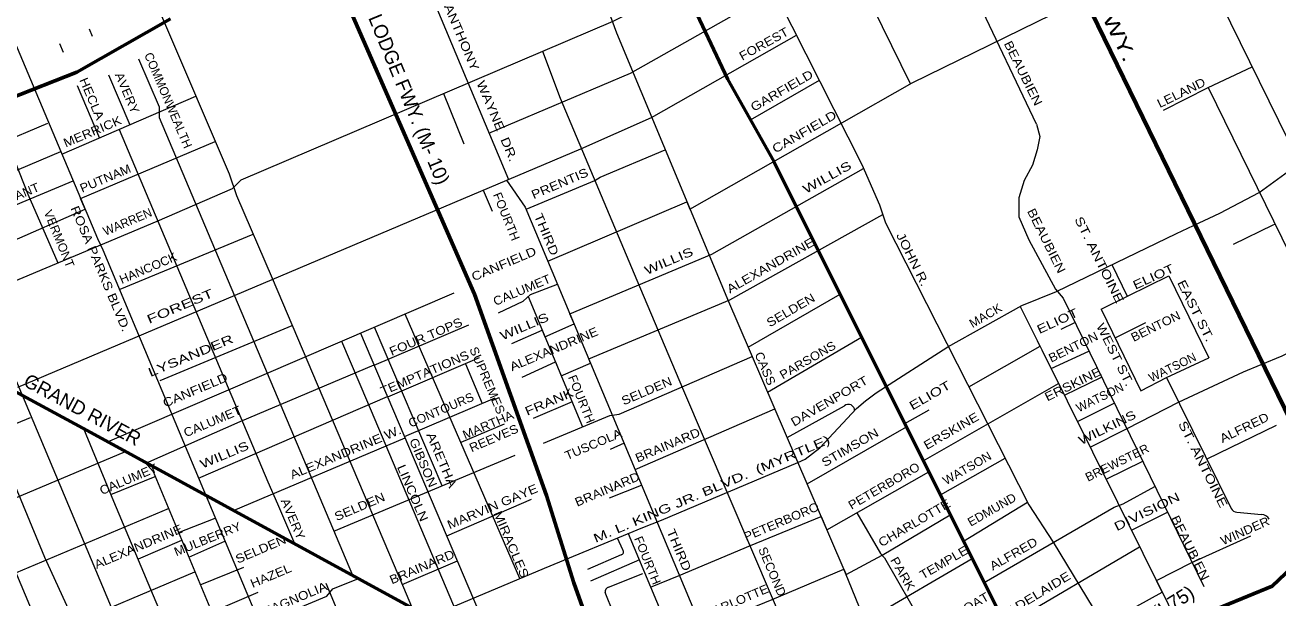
# Model space of a CAD drawing. Extents: x 34705 to 138605, y 34275 to 143551.
# Drawn here: x 89542 to 100351, y 103945 to 108885 of the extents above; entities that cross this region are included whole.
import ezdxf
from ezdxf.enums import TextEntityAlignment as Align

# ---------------------------------------------------------------- set-up
doc = ezdxf.new("R2010")
doc.units = 0
doc.header["$LTSCALE"] = 30
for name, color, linetype, lineweight in [('1', 7, 'Continuous', 13), ('11', 7, 'Continuous', 13), ('51', 7, 'Continuous', 35)]:
    doc.layers.add(name, color=color, linetype=linetype, lineweight=lineweight)

msp = doc.modelspace()

# ---------------------------------------------------------------- linework, layer by layer
at = {"layer": '1'}
for p, q in [((98268.09, 108031.24), (96714.25, 111289.53)), ((97195.08, 108386.28), (98669.87, 109111.42)), ((90094.68, 108851.47), (90120.89, 108789.79)), ((89838.85, 108726.79), (89871.1, 108650.47)), ((99750.13, 108345.09), (100128.24, 108524.33)), ((90262.96, 108455.55), (90446.24, 108024.38)), ((89992.73, 108362.68), (90183.76, 107910.7)), ((95800.35, 108066.32), (96394.86, 108409.99)), ((93152.95, 108294.54), (93327.47, 107861.91)), ((89063.37, 107752.52), (89737.65, 108039.92)), ((88037.22, 107540.27), (90948.84, 100639.76)), ((89271.92, 107254.92), (89956.65, 107542.35)), ((93494.54, 107462.47), (93571.5, 107280.51)), ((99476.25, 107088.15), (99622.96, 107156.95)), ((90361.57, 106607.54), (91510.38, 107081.43)), ((98919.57, 106819.11), (99051.55, 106546.97)), ((99060.17, 106551.15), (99410.54, 106722.32)), ((99410.54, 106722.32), (99755.93, 106015.44)), ((90254.41, 105291.57), (93244.99, 106574.95)), ((93882.8, 106543.11), (94351.99, 105420.76)), ((95780.55, 106107.06), (96574.52, 106563.39)), ((98826.13, 106434.13), (99060.17, 106551.15)), ((93812.34, 104112.95), (92821.35, 106393.15)), ((98826.13, 106434.13), (99169.3, 105731.8)), ((90707.67, 105821), (91848, 106294.07)), ((92555.43, 105951.17), (93372.26, 106299.14)), ((93140.31, 104911.52), (92557.83, 106280.07)), ((98482.05, 106262.07), (98599.25, 106320.68)), ((98945.95, 106188.91), (99210.33, 106321.11)), ((92437.6, 106228.47), (93613.46, 103461.04)), ((95948.17, 105718.52), (96759.8, 106192.63)), ((98299.54, 106114.59), (98277.06, 106159.57)), ((97685.09, 105764.32), (98299.54, 106114.59)), ((98395.14, 105922.3), (98720.71, 106072.11)), ((92671.46, 105678.09), (93464.13, 106017.69)), ((93341.29, 105965.06), (93486.33, 105622.5)), ((98508.94, 105692.45), (98829.38, 105849.71)), ((99389.68, 105844.93), (99949.07, 104716.79)), ((96792.71, 105644.68), (96885.15, 105714.56)), ((97291.93, 105127.73), (98458.89, 105793.94)), ((91038.93, 104979), (92670.27, 105680.89)), ((92815.81, 105338.34), (93598.22, 105669.92)), ((94261.97, 105636.08), (93926.96, 105492.82)), ((96716.8, 105577.81), (96792.71, 105644.68)), ((98621.13, 105467.27), (98939.78, 105623.75)), ((87940.41, 104815.15), (89589.87, 105502.16)), ((94805.77, 105052.37), (96009.93, 105575.32)), ((96115.98, 105329.5), (96610.87, 105602.03)), ((97131.52, 105448.74), (97341.23, 105568.3)), ((93674.78, 105442.79), (93303.16, 105284.53)), ((96289.23, 104927.89), (97145.81, 105420.13)), ((99739.75, 105143.49), (100339.65, 105434.57)), ((91340.91, 104699.96), (92821.66, 105324.57)), ((94710.75, 105279.08), (94589.3, 105224.13)), ((92207.61, 104519.53), (93772.07, 105177.04)), ((95033.53, 104614.61), (96209.46, 105112.79)), ((96209.46, 105112.79), (96273.4, 105140.29)), ((97439.28, 104832.85), (97997.48, 105150.12)), ((98868.77, 104968.69), (99184.41, 105123.1)), ((90281.25, 104836.21), (90665.41, 104992.53)), ((94585.62, 104809.59), (94862, 104918.2)), ((93180.91, 104479.06), (93911.95, 104795.23)), ((97637.63, 104435.9), (98189.75, 104772.08)), ((87580.9, 103369.15), (90780.2, 104717.28)), ((90866.81, 104508.8), (91183.12, 104633.11)), ((99086.69, 104529.92), (99398.13, 104685.69)), ((99997.85, 104684.82), (100209.21, 104664.52)), ((94870.72, 104551.4), (95033.53, 104614.61)), ((90521.46, 104281.06), (90894.05, 104443.38)), ((90954.85, 104297.34), (91266.47, 104434.49)), ((94700.64, 104358.37), (94652.42, 104461.37)), ((94745.68, 104500.34), (95648.75, 102345.66)), ((94686.23, 104316.6), (94395.44, 104191.29)), ((98002.36, 103706.01), (99158.2, 104385.92)), ((91054.04, 104059.11), (91428.49, 104211.27)), ((92796.63, 104061.99), (93272.21, 104264.18)), ((94843.86, 104272.69), (94420.3, 104088.29)), ((96956.14, 104289.35), (97774.44, 102874.49)), ((92198.44, 104022.64), (92418.5, 104112.49)), ((94577.26, 104038.12), (94871.2, 104156.65)), ((91152.1, 103823.55), (91552.57, 103996.12)), ((94619.68, 103812.39), (94546.47, 103991.39))]:
    msp.add_line(p, q, dxfattribs=at)
at = {"layer": '1', "lineweight": 53}
msp.add_line((90110.84, 105370.56), (94629.96, 102906.87), dxfattribs=at)
at = {"layer": '1'}
for points in [[(89474.59, 122846.01), (91544.38, 118695.87), (91485.34, 118525.26), (91445.98, 118334.96), (92122.6, 116967.52), (92180.3, 116877.74), (93371.26, 114453.63), (94086.27, 113029.71), (94119.06, 112950.97), (94335.54, 112517.89), (95799.33, 109586.03), (95857.03, 109444.94), (96036.54, 109117.87), (96762.63, 107683.46), (96913.51, 107335.68), (96965.99, 107178.2), (98202.49, 104747.04), (98412.4, 104425.51), (98930.62, 103572.47), (99211.35, 103092.72)], [(81747.75, 122290.24), (81921.27, 121957.09), (82052.47, 121930.85), (82118.06, 121884.91), (82590.36, 120959.69), (82629.72, 120926.88), (83141.38, 119927.85), (83541.52, 119133.87), (83541.52, 119022.31), (83495.61, 118937.01), (83436.57, 118877.95), (83449.69, 118733.59), (83456.25, 118661.41), (87277.28, 110821.66), (87605.27, 110172.03), (87736.46, 109929.24), (90285.3, 103864.22), (92725.99, 98068.68)], [(92090.21, 118673.57), (92344.66, 118157.79), (94015.45, 114820.73), (94775.04, 113275.79), (95103.02, 112606.48), (95332.61, 112140.59), (97179.3, 108381.96)], [(99622.96, 107156.95), (99848.68, 107262.79), (100188.92, 107440.65), (100537.2, 107693.33), (100968.9, 107962.79), (103779.62, 109348.23), (104572.5, 109741.16), (105072.96, 109985.65), (105247.54, 110090.43), (106097.16, 110492.09), (110265.23, 112549.88), (110957.73, 112899.15), (112028.48, 113475.45), (113105.05, 114057.56), (114210.72, 114761.93)], [(92402.65, 113894.18), (92751.37, 113182.28), (92816.97, 113064.17), (92902.24, 112946.05), (92967.84, 112775.44), (93151.51, 112329.24), (94584.81, 108982.71), (94643.84, 108818.66), (95260.46, 107342.24), (95601.56, 106522.01), (96598.64, 104210.61), (96644.56, 104099.06), (97018.46, 103180.4), (97300.53, 102491.4), (97891.97, 101138.22)], [(91170.47, 113339.76), (91288.55, 113261.02), (91767.41, 112276.74), (91819.89, 112125.82), (91839.57, 112020.83), (91905.16, 111784.6), (91964.2, 111600.87), (92101.96, 111312.15), (92213.47, 111134.98), (92285.63, 111016.87), (92416.82, 110733.08), (92672.65, 110175.32), (92725.13, 109958.78), (92803.85, 109722.55), (93711.92, 107554.46)], [(87924.47, 112104.52), (87935.44, 111856.64), (88221.88, 111308.88), (88769.61, 110355.76), (90167.23, 107043.23), (90212.11, 106947.03), (92757.3, 100881.83), (92968.86, 100445.74), (93020.15, 100349.54), (93007.33, 100272.59), (93410.61, 99313.84), (93470.43, 99278.08), (94003.29, 98018.06), (94007.57, 97912.37), (94251.36, 97332.72)], [(89620.31, 111530.82), (91301.99, 107601.17), (91366.1, 107415.19), (91673.83, 106703.33), (92808.58, 104033.88), (93975.39, 101263.41), (94552.01, 99871.59), (94676.64, 99628.81), (94945.59, 99182.6), (95948.05, 97457.03)], [(93544.68, 107953.77), (94766.98, 108470.68), (96621.13, 109518.01)], [(74914.4, 104874.31), (75879.58, 104897.58), (77259.02, 104781.25), (77456.7, 104757.99), (78323.04, 104711.46), (84801.63, 104845.23), (85092.35, 104868.5), (85377.25, 104932.47), (86652.03, 105479.2), (88419.59, 106217.85), (88564.94, 106305.1), (90681.35, 107194.97), (91332.56, 107474.15), (91408.14, 107549.76), (94615.68, 108918.91), (95226.7, 109227.44), (95367, 109272.3)], [(99858.25, 109072.97), (101846.54, 105032.72), (101949.12, 104782.61), (102115.8, 104423.47), (102367.74, 103949.45)], [(89480.37, 105763.72), (94336.35, 107818.71), (94947.38, 108086.49), (96198.55, 108797.8)], [(94005.91, 108658.63), (94158.42, 108254.34), (94820.96, 106686.06), (95214.54, 105754.27), (96190.89, 103469.22)], [(90522.15, 108593.43), (90698.17, 108180.52), (90698.17, 108088.65), (92367.36, 104140.37)], [(94052.23, 106850.36), (95252.26, 107361.86), (95278.76, 107298.24), (96589.88, 108042.83), (97195.08, 108386.28)], [(99364.51, 108152.23), (99750.13, 108345.09), (100384.82, 107049.64), (101453.37, 104861.55)], [(99364.51, 108152.23), (99750.13, 108345.09), (100384.82, 107049.64), (101442.45, 104883.91)], [(99364.51, 108152.23), (99750.13, 108345.09), (100384.82, 107049.64), (101464.42, 104838.92)], [(88822.18, 107335.87), (89175.45, 107491.6), (89204.52, 107520.68), (89849.99, 107795.14), (89860.49, 107770.24), (91015.38, 108270.9)], [(89306.48, 108074.95), (89566.63, 107427.55), (89826.05, 106835.35)], [(90355.43, 107985.05), (91636.21, 104947.17), (91721.49, 104756.87), (91867.34, 104412.97)], [(98268.09, 108031.24), (98296.43, 107925.03), (98274.65, 107808.14), (98235.29, 107676.9), (98163.13, 107545.66), (98117.21, 107394.74), (98117.21, 107230.69), (98202.49, 107033.84), (98432.08, 106607.32), (98497.68, 106528.57), (99711.23, 104044.92)], [(88986.64, 106954.4), (89336.78, 107100.15), (89379.83, 106997.43), (90060.09, 107297.16), (90021.38, 107388.91), (91182.55, 107880.27)], [(93864.6, 107298.05), (94458.56, 107545.12), (94505.11, 107574.22), (95065.61, 107808.79)], [(93742.41, 106137.57), (94003.94, 106253.34), (94027.36, 106197.32), (94278.8, 106309.76), (94243.06, 106395.04), (95466.53, 106909.98), (96774.75, 107648.64)], [(93695.7, 107547.6), (93857.2, 107315.71), (95985.91, 102236.51)], [(93830.01, 105849.94), (94118.32, 105979.73), (94168.42, 105859.88), (94421, 105970.47), (94406.15, 106005.88), (95623.51, 106514.48), (96941.38, 107252.03)], [(99967.16, 106994.24), (100311.32, 107162.37), (100324.93, 107169.07)], [(96885.15, 105714.56), (97503.51, 106110.2), (98140.51, 106466.1), (98440.41, 106587.53), (99476.25, 107088.15)], [(93627.3, 106404.33), (93838.52, 106502.85), (93902.48, 106561.01), (94136.06, 106650.35)], [(98127.48, 106458.82), (98314, 106085.66), (99403.93, 103891.18), (99544.97, 103583.35), (99595.15, 103504.77)], [(100207.62, 105958.03), (100386.97, 106033.07), (100771.04, 106225.17), (100840.88, 106265.91), (101155.71, 106436.5)], [(89318.01, 106151.54), (89120.57, 106072.53), (89061.53, 105947.86), (89061.53, 105862.55), (89709.3, 104295.91), (89979.33, 103708.16), (90424.31, 102635.76), (90450.55, 102570.15)], [(92273.44, 106158.02), (92495.54, 105632.89), (93356.65, 103601.04)], [(90584.73, 105107.33), (91399.42, 105467.56), (92553.8, 105955)], [(94015.76, 105279.45), (94586.58, 105519.35), (94668.05, 105530.99), (95814.89, 106027.46)], [(98730.8, 105246.46), (99051.44, 105405.83), (99493.71, 105632.86), (100054.7, 105894.04), (100207.62, 105958.03)], [(99169.3, 105731.8), (99389.9, 105845.04), (99755.93, 106015.44)], [(96273.4, 105140.29), (96399.9, 105238.19), (96716.8, 105577.81)], [(90045.33, 105405.98), (90304.59, 104779.85), (90859.58, 103460.99)], [(79819.31, 100347.1), (80849.35, 100888.78), (81157.51, 101063.26), (81390.09, 101179.59), (82385.53, 101727.1), (82404.38, 101691.59), (83852.83, 102468.28), (83914.13, 102353.8), (84532.72, 102680.17), (84619.93, 102761.59), (84869.95, 102889.55), (85242.07, 103052.4), (85300.21, 103052.4), (86410.74, 103506.06), (87338.12, 103914.64), (90408.69, 105206.69)], [(90576.58, 105116.66), (90647.47, 105035.61), (91251.37, 103585.13)], [(94939.42, 104038.08), (95184.51, 104139.73), (95801.36, 104395.86), (96410.38, 104647.02), (96459.66, 104532.78), (97340.13, 105031.27)], [(97817.09, 104076.77), (98939.76, 104727.12), (99015.56, 104757.45), (99290.52, 104905.94)], [(95144.29, 103549.28), (95370.73, 103656.57), (95446.38, 103708.96), (95987.58, 103930.16), (96605.73, 104193.38), (96625.21, 104146.06), (96936.12, 104314.36), (97524.26, 104662.79)], [(96717.5, 104678.76), (96923.34, 104328.72), (96956.14, 104289.35)], [(90156.4, 102571.65), (94024.26, 104202.29), (94870.72, 104551.4)], [(98181.84, 103346.84), (99351.96, 103995.82), (99302.9, 104094.6), (99608.67, 104250.66), (100118.87, 104480.34)], [(90738.5, 101138.28), (92958.63, 102086.3), (93540.56, 102319.15), (94588.03, 102755.74), (94861.54, 102907.09), (96744.08, 103703.14), (96837.19, 103772.99), (97713.93, 104285.09)], [(87827, 102821.34), (88640.53, 103170.17), (91008.18, 104169.25)], [(91251.37, 103585.13), (92146.6, 103961.27), (92198.44, 104022.64)], [(92137.1, 104071.39), (93174.01, 101584.06), (93353.56, 101153.61)]]:
    msp.add_lwpolyline(points, dxfattribs=at)
at = {"layer": '1', "lineweight": 53}
for points in [[(88660.55, 122435.75), (92843.2, 114028.76), (93335.18, 113024.79), (93440.14, 112782.01), (93902.59, 111904.36), (94112.5, 111523.77), (94525.77, 110657.61), (94939.03, 109837.38), (95188.3, 109345.24), (95267.02, 109133.63), (95601.56, 108418.39), (96001.71, 107709.71), (99029.01, 101651.49), (99866.2, 100204.4)], [(81141.26, 110244.39), (85447.32, 107891.61), (90110.84, 105370.56)]]:
    msp.add_lwpolyline(points, dxfattribs=at)
at = {"layer": '1'}
for centre, radius, start, end in [((96645.05, 105560), 54.17, 358.90575, 129.11156), ((99999.82, 104741.02), 56.24, 205.5248, 267.9903), ((100210.68, 104592.46), 72.07, 26.80006, 91.17398), ((94678.15, 104342.76), 27.38, 287.16115, 34.7633), ((94591.96, 103994.93), 45.63, 108.79235, 184.44263)]:
    msp.add_arc(centre, radius, start, end, dxfattribs=at)
at = {"layer": '51', "lineweight": 60}
for points in [[(89237.66, 115479.85), (91499.64, 110952.67), (93420.76, 106565.37), (94042.42, 104827.01), (94275.43, 104074.61), (94754.53, 102737.63), (94761.52, 102513.8), (95607.58, 100567.59), (95901.26, 100112.95), (96166.96, 99847.16), (96705.36, 99210.66), (97075.95, 98895.9), (97236.78, 98686.07), (97390.6, 98581.15), (97562.53, 98387.67)], [(87067.87, 107328.8), (89988.97, 108477.92), (90798.22, 108939.62)], [(100708.3, 104431.99), (100301.7, 104046.37), (99460.75, 103701.33), (98388.89, 103068.27), (97510.88, 102543.58), (96878.03, 102018.88), (96266.56, 101672.41), (94157.06, 101062.17), (92788.73, 100605.91), (92053.25, 100332.16), (91322.06, 100332.16), (90426.94, 100400.6), (89697.17, 100337.86), (89332.28, 99932.93), (89286.67, 99488.08), (89309.48, 99071.74), (89383.59, 98792.29), (89913.82, 97593.19), (90193.19, 96937.32), (90347.13, 96349.89), (90369.93, 95910.74)]]:
    msp.add_lwpolyline(points, dxfattribs=at)
at = {"layer": '51', "lineweight": 70}
msp.add_lwpolyline([(97910.12, 110708.17), (100683.69, 105015.92), (100740.7, 104462.71), (100708.3, 104431.99)], dxfattribs=at)

# ---------------------------------------------------------------- texts
at = {"layer": '11'}
for s, height, rotation, width, p in [('CHRYSLER FWY.', 120, 296.26, 1.45, (98604.73, 109412.12)), ('ANTHONY   WAYNE  DR.', 75, 292.998, 1.25, (93440.68, 108372.61)), ('FOREST', 75, 29.017, 1.15, (95934.21, 108689.73)), ('BEAUBIEN', 75, 296.46, 1.2, (98120.07, 108453.33)), ('HECLA', 75, 293.107, 1.15, (90084.67, 108234.86)), ('AVERY', 75, 293.097, 1.1, (90389.05, 108284.85)), ('GARFIELD', 75, 30.017, 1.2, (96089.74, 108287.12)), ('LELAND', 75, 26.216, 1.15, (99533.59, 108267.59)), ('MERRICK', 75, 22.848, 1.15, (90138.02, 107932.49)), ('CANFIELD', 75, 30.018, 1.25, (96283.72, 107932.05)), ('PUTNAM', 75, 22.817, 1.1, (90249.5, 107528.75)), ('WILLIS', 75, 28.998, 1.4, (96479.78, 107539.5)), ('PRENTIS', 75, 22.997, 1.2, (94170.08, 107484.3)), ('BRYANT', 75, 22.808, 1.1, (89468.51, 107371.65)), ('FOURTH', 75, 292.14, 1.05, (93660.58, 107219.93)), ('VERMONT', 75, 292.318, 1.05, (89801.83, 107028.08)), ('ROSA PARKS BLVD.', 75, 292.857, 1.2, (90158.81, 106769.78)), ('THIRD', 75, 292.938, 1.25, (94006.49, 107065.53)), ('BEAUBIEN', 75, 296.46, 1.2, (98320.42, 107008.41)), ('ST. ANTOINE', 75, 296.46, 1.3, (98776.42, 106844.1)), ('ALEXANDRINE', 75, 29.753, 1.2, (95991.68, 106779.14)), ('JOHN R.', 75, 296.46, 1.25, (97167.39, 106848.9)), ('HANCOCK', 75, 23.196, 1.05, (90618.85, 106755.32)), ('CANFIELD', 75, 22.955, 1.2, (93687.33, 106790.96)), ('WILLIS', 75, 22.999, 1.35, (95110.21, 106815.93)), ('ELIOT', 75, 24.683, 1.3, (99292.42, 106681.04)), ('CALUMET', 75, 23.002, 1.1, (93843.08, 106565.53)), ('EAST ST.', 75, 296.46, 1.3, (99608.68, 106404.82)), ('FOREST       ', 75, 22.799, 1.5, (91028.86, 106482.49)), ('SELDEN', 75, 30.304, 1.15, (96166.58, 106393.62)), ('MACK', 75, 30.304, 1.05, (97847.54, 106347.61)), ('WILLIS', 75, 22.999, 1.35, (93864.46, 106251.68)), ('ELIOT', 75, 24.683, 1.3, (98464.44, 106298.91)), ('BENTON', 75, 26.24, 1.1, (99312.46, 106253.7)), ('FOUR TOPS', 75, 23.235, 1.15, (93014.67, 106163.36)), ('ALEXANDRINE', 75, 22.733, 1.15, (94119.33, 106057.1)), ('WEST ST.', 75, 296.46, 1.25, (98912.89, 106026.64)), ('LYSANDER     ', 75, 22.576, 1.45, (91078.49, 106038.78)), ('PARSONS', 75, 30.304, 1.1, (96312.9, 105963.8)), ('BENTON', 75, 26.24, 1.1, (98601.68, 106075.04)), ('TEMPTATIONS', 75, 23.235, 1.15, (93004.31, 105849.71)), ('SUPREMES', 75, 293.235, 1.1, (93495.93, 105806.25)), ('CASS', 75, 292.933, 1.1, (95893.45, 105908.64)), ('ERSKINE', 75, 26.24, 1.2, (98598.92, 105755.47)), ('CANFIELD', 75, 22.955, 1.2, (91024.5, 105702.57)), ('FOURTH', 75, 292.14, 1.05, (94308.3, 105645.91)), ('SELDEN', 75, 23.066, 1.15, (94919.57, 105695.36)), ('DAVENPORT ', 75, 30.304, 1.2, (96514.36, 105617.84)), ('ELIOT', 75, 29.976, 1.35, (97367.04, 105659.07)), ('CONTOURS', 75, 23.235, 1.05, (93146.06, 105531.86)), ('FRANK ', 75, 22.923, 1.3, (94094.66, 105608.19)), ('CALUMET', 75, 23.024, 1.1, (91172.6, 105432.8)), ('MARTHA', 75, 23.236, 1.1, (93551.41, 105403.26)), ('ERSKINE', 75, 29.979, 1.2, (97550.8, 105352.41)), ('WILKINS', 75, 26.24, 1.3, (98894.9, 105380.86)), ('ALFRED', 75, 25.946, 1.15, (100077.37, 105379.92)), ('ALEXANDRINE W.', 75, 22.744, 1.2, (92321.68, 105165.75)), ('REEVES', 75, 23.236, 1.1, (93600.72, 105288.4)), ('TUSCOLA', 75, 23.065, 1.1, (94458.43, 105234.55)), ('BRAINARD', 75, 23.066, 1.15, (95100.72, 105228.61)), ('STIMSON', 75, 30.303, 1.2, (96678.26, 105209.92)), ('ST. ANTOINE', 75, 296.46, 1.3, (99671.47, 105080.94)), ('WILLIS', 75, 22.67, 1.35, (91276.59, 105144.61)), ('GIBSON', 75, 293.034, 1.15, (92943.15, 105097.03)), ('ARETHA ', 75, 293.085, 1.25, (93109.03, 105102.95)), ('M. L. KING JR. BLVD.  (MYRTLE)', 75, 22.999, 1.45, (95479.84, 104850.3)), ('WATSON', 75, 29.978, 1.05, (97687.75, 105031.53)), ('BREWSTER', 75, 26.237, 1.05, (98980.08, 105077.87)), ('CALUMET', 75, 22.885, 1.1, (90448.3, 104934.12)), ('LINCOLN', 75, 293.191, 1.2, (92852.38, 104835.19)), ('PETERBORO', 75, 30.303, 1.1, (96971.49, 104878.64)), ('BRAINARD', 75, 23.065, 1.15, (94579.38, 104847.89)), ('SELDEN', 75, 23.04, 1.15, (92443.52, 104697.4)), ('MARVIN GAYE', 75, 22.878, 1.2, (93588.98, 104698.58)), ('DIVISION', 75, 26.24, 1.4, (99237.14, 104655.7)), ('AVERY', 75, 292.918, 1.1, (91819.76, 104611.26)), ('PETERBORO', 75, 23.066, 1.1, (96081.83, 104568.93)), ('CHARLOTTE', 75, 30.47, 1.15, (97232.87, 104559)), ('EDMUND', 75, 29.843, 1.05, (97901.56, 104673.52)), ('MIRACLES', 75, 293.235, 1.2, (93702.46, 104391.77)), ('BEAUBIEN', 75, 296.46, 1.2, (99561.47, 104360.75)), ('WINDER', 75, 23.999, 1.1, (100082.01, 104489.07)), ('ALEXANDRINE', 75, 23.093, 1.15, (90533.71, 104353.15)), ('MULBERRY', 75, 22.174, 1.1, (91130.79, 104419.14)), ('THIRD', 75, 292.938, 1.25, (95149.37, 104344.3)), ('SELDEN', 75, 23.04, 1.15, (91589.85, 104330.31)), ('FOURTH', 75, 292.14, 1.05, (94878.46, 104254.93)), ('ALFRED', 75, 29.849, 1.15, (98088.8, 104293)), ('BRAINARD', 75, 23.009, 1.15, (92981.08, 104178.08)), ('SECOND', 75, 292.931, 1.05, (95954.27, 104157.53)), ('TEMPLE', 75, 30.044, 1.15, (97487, 104217.98)), ('HAZEL', 75, 22.885, 1.15, (91676.78, 104101.7)), ('PARK', 75, 299.88, 1.15, (97082.12, 104135.74)), ('ADELAIDE', 75, 31.437, 1.25, (98306.17, 103951.75)), ('MAGNOLIA', 75, 22.958, 1.15, (91877.38, 103898.61)), ('CHARLOTTE', 75, 23.07, 1.1, (95657.15, 103864.92)), ('SPROAT', 75, 30.043, 1.15, (97662.81, 103813.57))]:
    msp.add_text(s, height=height, rotation=rotation, dxfattribs=dict(at, width=width)).set_placement(p, align=Align.CENTER)
for s, height, rotation, p in [('LODGE FWY. (M- 10)', 120, 292.379, (92800.3, 108222)), ('COMMONWEALTH', 75, 293.083, (90742.63, 108221.16)), ('WARREN', 75, 22.973, (90440.09, 107154.16)), ('WATSON', 75, 25.985, (99456.92, 105900.41)), ('GRAND RIVER', 120, 331.713, (90009.31, 105515.47)), ('WATSON', 75, 25.985, (98830.99, 105640.73)), ('FISHER FWY. (I-75)', 120, 31.894, (99023.1, 103570.89))]:
    msp.add_text(s, height=height, rotation=rotation, dxfattribs=at).set_placement(p, align=Align.CENTER)

doc.saveas('drawing.dxf')
